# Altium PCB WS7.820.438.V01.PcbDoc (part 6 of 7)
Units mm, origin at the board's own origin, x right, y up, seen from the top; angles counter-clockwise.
Board outline 143.01 x 224 mm, 4 copper layers (Top Layer, G2, S3, Bottom Layer); 863 components, 638 nets, 2623 pads, 4664 vias.
Unrouted connection lines stored in the file: 16.
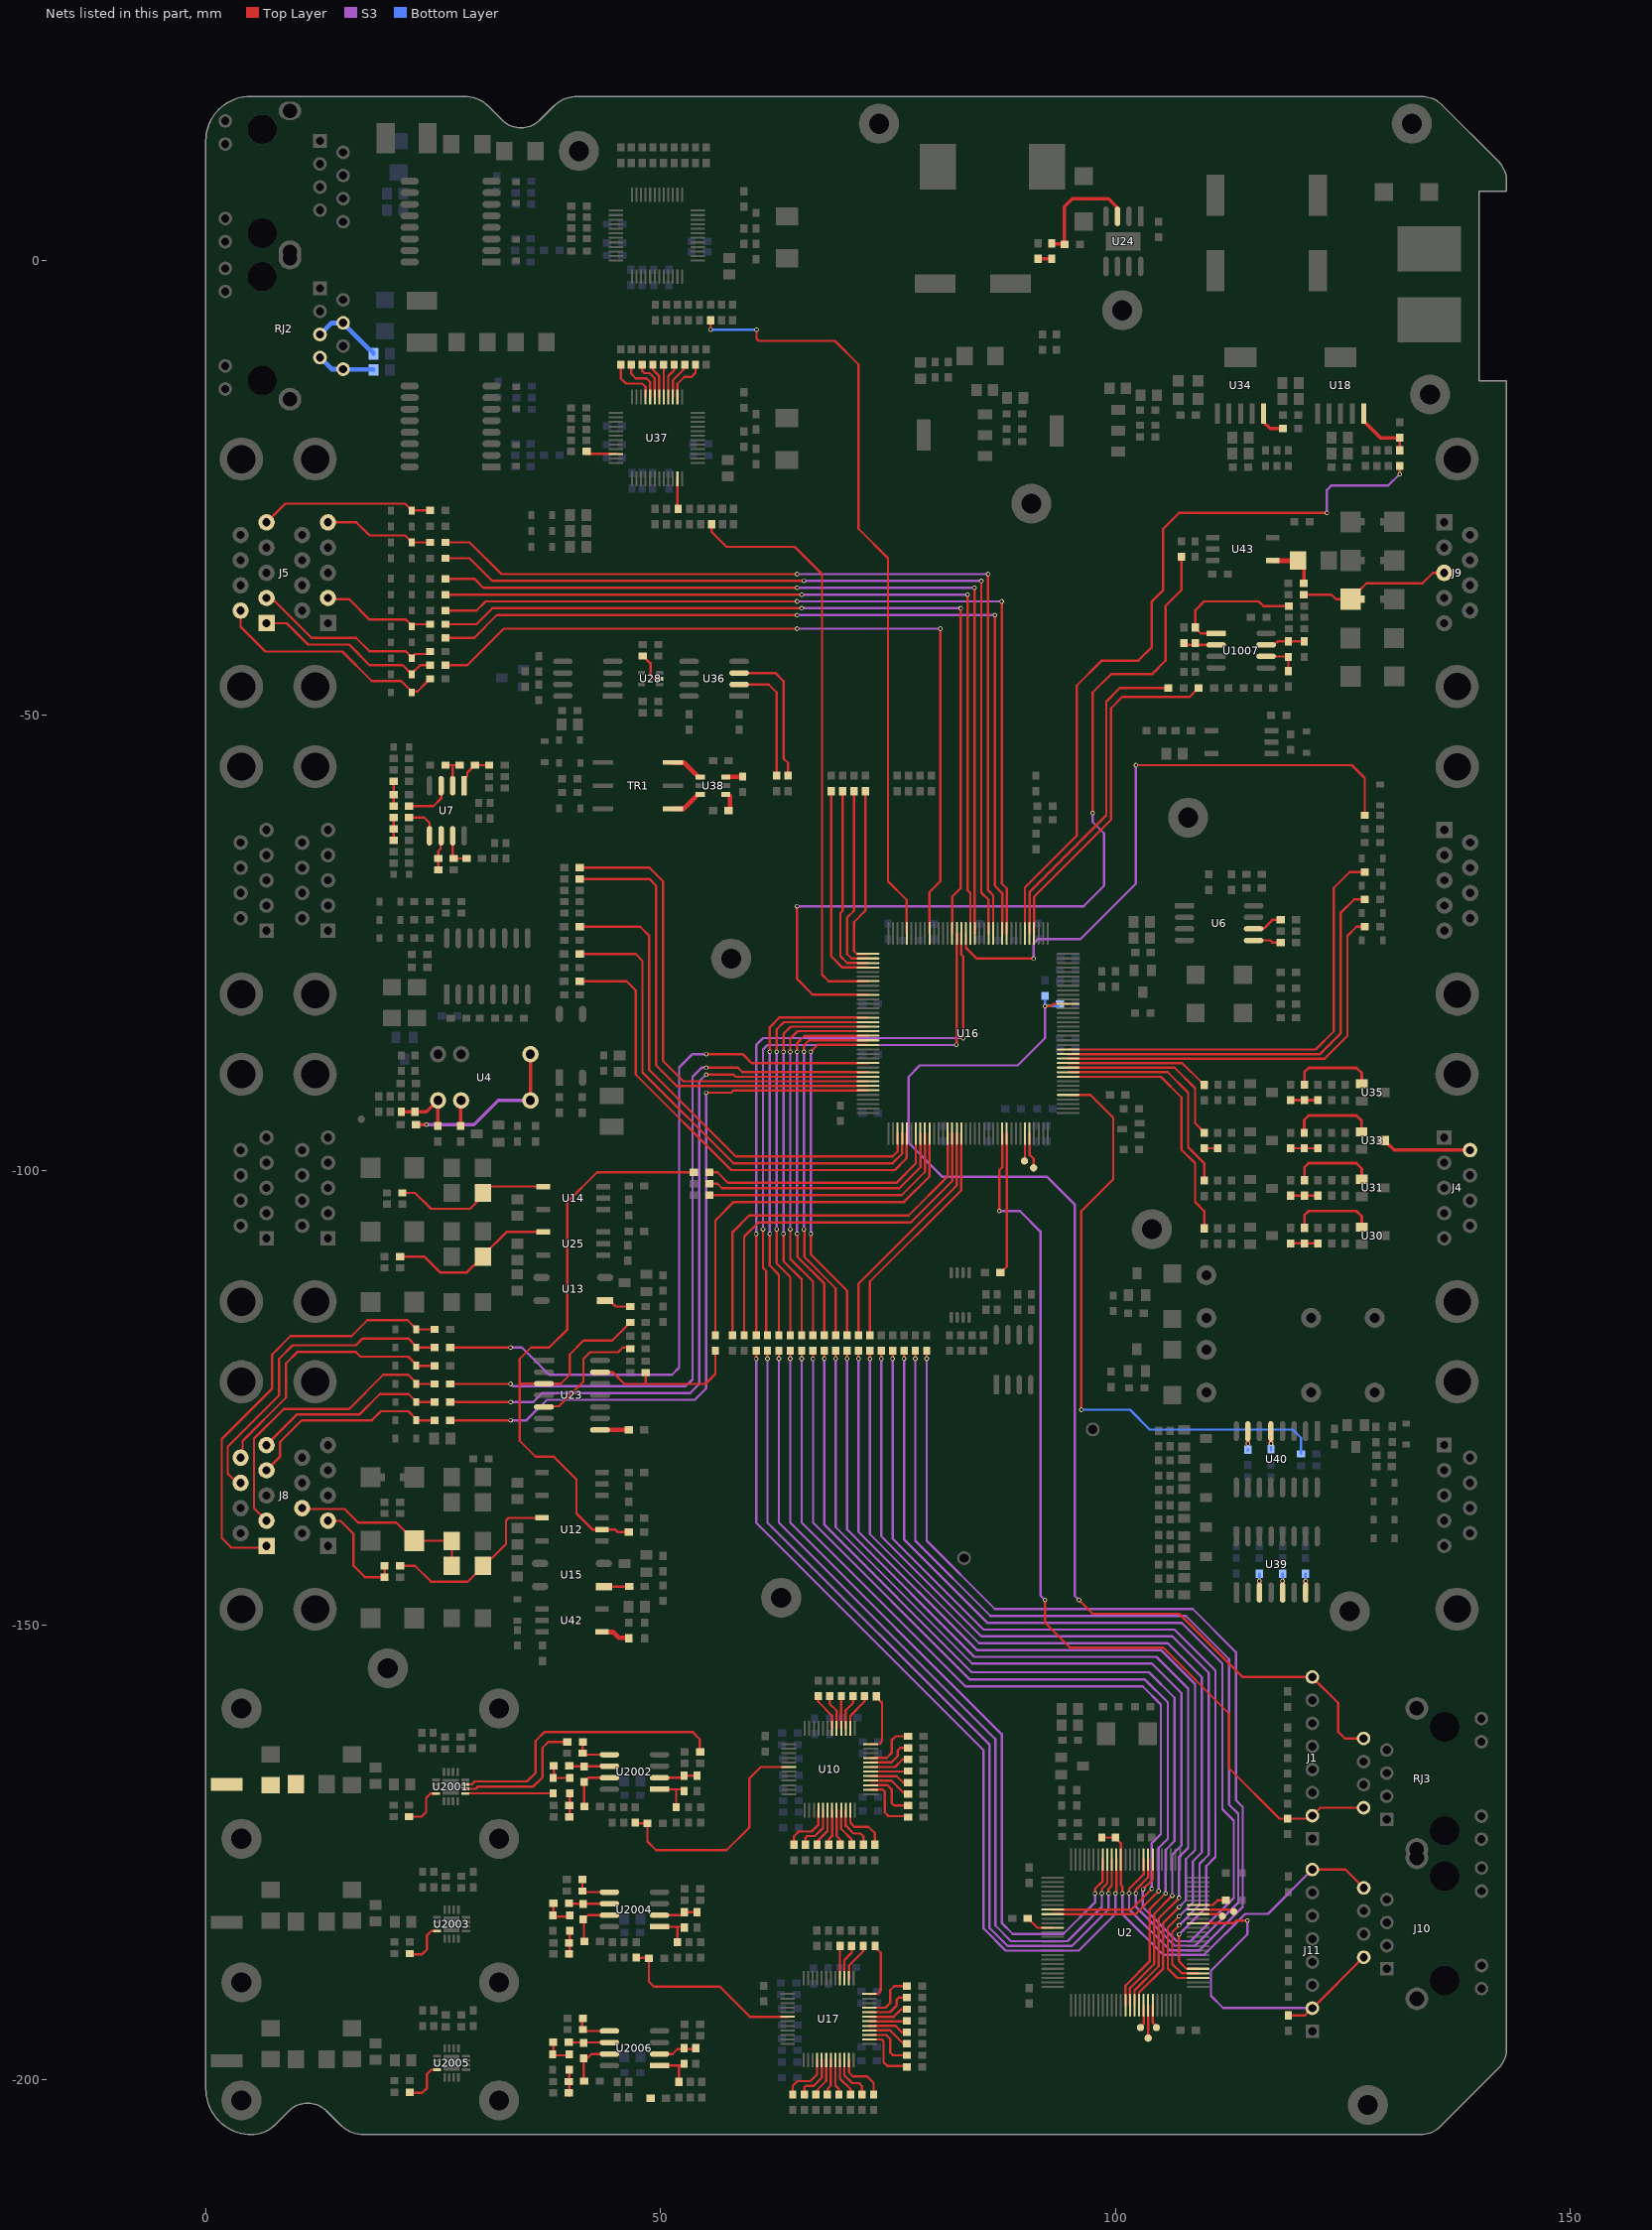
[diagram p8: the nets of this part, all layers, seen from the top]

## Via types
v1: diameter 0.508, hole 0.305, Top Layer to Bottom Layer, tented both sides, 4404 vias
v2: diameter 0.508, hole 0.3, Top Layer to Bottom Layer, tented both sides, 200 vias
v3: diameter 0.813, hole 0.508, Top Layer to Bottom Layer, tented both sides, 31 vias
v4: diameter 0.457, hole 0.305, Top Layer to Bottom Layer, tented both sides, 10 vias
v5: diameter 0.66, hole 0.406, Top Layer to Bottom Layer, tented both sides, 9 vias
v6: diameter 0.762, hole 0.406, Top Layer to Bottom Layer, tented both sides, 6 vias
v7: diameter 0.711, hole 0.406, Top Layer to Bottom Layer, tented both sides, 4 vias

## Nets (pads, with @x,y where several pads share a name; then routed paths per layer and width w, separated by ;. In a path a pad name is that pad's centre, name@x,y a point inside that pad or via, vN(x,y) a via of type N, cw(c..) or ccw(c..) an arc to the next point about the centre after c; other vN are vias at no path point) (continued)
NetR92_1: R92.1 U6.6 | length 3.4
  Top Layer w0.254: U6.6@115.19,-73.49 115.256,-73.424 116.326,-73.424 117.25,-72.5 R92.1@118.15,-72.5
NetR93_1: R93.1 U6.5 | length 3.1
  Top Layer w0.254: U6.5@115.19,-74.76 115.201,-74.75 117,-74.75 117.25,-75 R93.1@118.15,-75
NetR94_2: R94.2 U16.125 | length 26.5
  Top Layer w0.254: R94.2@73,-118.359 R94.2@73,-118.15 73,-112.25 83.051,-102.199 U16.125@83.051,-95.987
NetR95_2: R95.2 U16.124 | length 26.8
  Top Layer w0.254: R95.2@71.75,-118.3 71.75,-112.5 82.551,-101.699 U16.124@82.551,-95.987
NetR96_2: R96.2 U16.40 | length 38.8
  Top Layer w0.254: U16.40@91.051,-73.987 91.051,-69.949 99.5,-61.5 99.5,-49.25 100.75,-48 108.15,-48 R96.2@109.15,-47
NetR97_2: R97.2 U16.41 | length 36.4
  Top Layer w0.254: U16.41@90.551,-73.987 90.551,-69.449 99,-61 99,-48.5 100.5,-47 R97.2@105.75,-47
NetR98_2: R98.2 U16.93 | length 39.4
  Top Layer w0.254: v1(66.5,-107) 66.5,-109.25 70.5,-113.25 R98.2@70.5,-118.15 ; v1(66.5,-87) 67.261,-86.239 ; 67.25,-86.239 67.261,-86.239 ; U16.93@72.75,-86.239 67.261,-86.239
  S3 w0.254: v1(66.5,-107) v1(66.5,-87)
NetR99_1: R99.1 U17.40 | length 3.4
  Top Layer w0.254: U17.40@69.704,-188.809 69.704,-185.416 R99.1@69.724,-185.396
NetR100_2: R100.2 U16.92 | length 40.5
  Top Layer w0.254: v1(65.75,-106.5) 65.799,-106.549 65.799,-109.549 69.25,-113 R100.2@69.25,-118.15 ; v1(65.75,-87) 65.75,-86.288 66.311,-85.727 U16.92@72.75,-85.727
  S3 w0.254: v1(65.75,-106.5) v1(65.75,-87)
NetR101_1: R101.1 R166.1 U24.3 | length 12.9
  Top Layer w0.381: R166.1@93,1.85 93.05,1.8 94.35,1.8 R101.1@94.4,1.75 ; R101.1@94.4,2 94.4,5.9 95.25,6.75 99.25,6.75 100.181,5.819 100.181,4.867 U24.3@100.223,4.825
NetR102_1: R102.1 R166.2 | length 1.5
  Top Layer w0.381: R102.1@91.5,0.15 R166.2@93,0.15
NetR103_1: R103.1 R144.1 R146.2 U4.1 | length 7.5
  Top Layer w0.381: R103.1@21.5,-93.6 R144.1@23,-93.6 24.266,-93.6 U4.1@25.513,-92.354 ; R146.2@25.5,-95.15 25.513,-95.137 U4.1@25.513,-92.354 ; U4.1@25.5,-92.25 25.513,-92.263 U4.1@25.513,-92.354 ; U4.1@25.525,-92.341 U4.1@25.513,-92.354
NetR104_1: R104.1 U4.2 | length 2.7
  Top Layer w0.381: R104.1@28,-95.15 28.033,-95.117 28.033,-92.533 U4.2@28,-92.5
NetR105_2: R105.2 U42.1 | length 3.2
  Top Layer w0.508: U42.1@43.55,-150.77 44.77,-150.77 45.394,-151.394 46.494,-151.394 R105.2@46.5,-151.4
NetR106_1: R106.1 U16.10 | length 24.5
  Top Layer w0.254: U16.10@94.801,-89.237 105.737,-89.237 108,-91.5 108,-97.5 109.75,-99.25 R106.1@109.75,-101.15
NetR107_1: R107.1 U16.13 | length 45
  Top Layer w0.254: U16.13@94.801,-87.737 123.013,-87.737 125.5,-85.25 125.5,-74.25 126.5,-73.25 R107.1@127.4,-73.25
NetR111_2: R111.2 U16.91 | length 41.5
  Top Layer w0.254: v1(65,-107) 65.049,-107.049 65.049,-109.549 68,-112.5 R111.2@68,-118.15 ; v1(65,-87) 65,-86.038 65.801,-85.237 U16.91@72.801,-85.237
  S3 w0.254: v1(65,-107) v1(65,-87)
NetR112_1: R112.1 U17.39 | length 3.7
  Top Layer w0.254: U17.39@70.204,-188.809 70.204,-186.82 71.005,-186.019 71.005,-185.407 R112.1@70.994,-185.396
NetR113_2: R113.2 U16.90 | length 42.5
  Top Layer w0.254: v1(64.25,-106.5) 64.25,-109.75 66.75,-112.25 R113.2@66.75,-118.15 ; v1(64.25,-87) 64.25,-85.538 65.061,-84.727 ; 65.038,-84.727 65.061,-84.727 ; U16.90@72.75,-84.727 65.061,-84.727
  S3 w0.254: v1(64.25,-106.5) v1(64.25,-87)
NetR114_1: R114.1 U17.38 | length 4.1
  Top Layer w0.254: U17.38@70.704,-188.809 70.704,-187.428 72.264,-185.868 R114.1@72.264,-185.396
NetR115_1: R115.1 U16.56 | length 66.6
  Top Layer w0.254: R115.1@60.5,-118.15 v1(60.5,-107) ; U16.56@83.051,-73.987 83.051,-76.313 83.25,-76.512 v1(83.25,-85.5)
  S3 w0.254: v1(60.5,-107) 60.5,-86.25 61.25,-85.5 v1(83.25,-85.5)
NetR116_2: R116.2 U16.46 | length 98.3
  Top Layer w0.254: R116.2@26.35,-38.5 29.75,-38.5 30.75,-37.5 v1(65,-37.5) ; v1(87.5,-37.5) 87.5,-68.5 88.051,-69.051 U16.46@88.051,-73.987
  S3 w0.254: v1(65,-37.5) v1(87.5,-37.5)
NetR117_1: R117.1 U17.36 | length 6.5
  Top Layer w0.254: U17.36@72.954,-190.559 73.847,-190.559 74.201,-190.206 74.201,-186.031 R117.1@73.576,-185.406
NetR118_1: R118.1 U17.33 | length 5.9
  Top Layer w0.254: U17.33@72.954,-192.059 74.719,-192.059 75.247,-191.531 75.247,-190.125 75.69,-189.682 R118.1@77.055,-189.682
NetR119_2: R119.2 U16.89 | length 43.6
  Top Layer w0.254: v1(63.5,-107) 63.5,-110 65.5,-112 R119.2@65.5,-118.15 ; v1(63.5,-87) 63.5,-85.038 64.301,-84.237 U16.89@72.801,-84.237
  S3 w0.254: v1(63.5,-107) v1(63.5,-87)
NetR122_1: R122.1 U17.32 | length 5.1
  Top Layer w0.254: U17.32@72.954,-192.559 75.21,-192.559 75.933,-191.836 75.933,-191.201 76.182,-190.952 R122.1@77.055,-190.952
NetR123_1: R123.1 U16.57 | length 65.3
  Top Layer w0.254: v1(61.25,-106.5) 61.25,-110.75 61.603,-111.103 61.603,-118.003 R123.1@61.75,-118.15 ; v1(82.5,-86.217) 82.5,-86.148 82.551,-86.097 U16.57@82.551,-73.987
  S3 w0.254: v1(61.25,-106.5) 61.25,-86.75 61.75,-86.25 63,-86.25 82.467,-86.25 v1(82.5,-86.217)
NetR124_1: R124.1 U17.31 | length 4.4
  Top Layer w0.254: U17.31@72.954,-193.059 75.624,-193.059 76.462,-192.222 R124.1@77.055,-192.222
NetR125_1: R125.1 U17.30 | length 4.1
  Top Layer w0.254: U17.30@72.954,-193.559 76.987,-193.559 R125.1@77.055,-193.492
NetR126_1: R126.1 U17.29 | length 4.4
  Top Layer w0.254: U17.29@72.954,-194.059 75.808,-194.059 76.511,-194.762 R126.1@77.055,-194.762
NetR127_1: R127.1 U16.113 | length 53.2
  Top Layer w0.254: R127.1@41.1,-79.25 46.25,-79.25 47.25,-80.25 47.25,-89.5 57.75,-100 75.75,-100 77.051,-98.699 U16.113@77.051,-95.987
NetR128_1: R128.1 U16.112 | length 54.8
  Top Layer w0.254: R128.1@41.1,-76.25 47.25,-76.25 48,-77 48,-89.25 58,-99.25 75.5,-99.25 76.551,-98.199 U16.112@76.551,-95.987
NetR129_1: R129.1 U16.111 | length 56.2
  Top Layer w0.254: R129.1@41.1,-73.25 47.75,-73.25 48.75,-74.25 48.75,-89 58.25,-98.5 75.5,-98.5 76.051,-97.949 U16.111@76.051,-95.987
NetR130_1: R130.1 U17.28 | length 4.7
  Top Layer w0.254: U17.28@72.954,-194.559 75.237,-194.559 76.709,-196.032 R130.1@77.055,-196.032
NetR131_1: R131.1 U17.27 | length 5.9
  Top Layer w0.254: U17.27@72.954,-195.059 74.797,-195.059 75.247,-195.509 75.247,-197.008 75.541,-197.302 R131.1@77.055,-197.302
NetR132_1: R132.1 U17.26 | length 6.7
  Top Layer w0.254: U17.26@72.954,-195.559 74.306,-195.559 74.511,-195.763 74.511,-198.049 74.917,-198.456 76.939,-198.456 R132.1@77.055,-198.572
NetR133_2: R133.2 U17.16 | length 5.7
  Top Layer w0.254: R133.2@64.517,-201.603 64.517,-200.661 65.036,-200.142 66.459,-200.142 67.204,-199.396 U17.16@67.204,-197.809
NetR134_2: R134.2 U17.17 | length 5.1
  Top Layer w0.254: R134.2@65.787,-201.603 65.787,-200.839 65.976,-200.65 66.814,-200.65 67.704,-199.76 U17.17@67.704,-197.809
NetR135_2: R135.2 U17.18 | length 4.3
  Top Layer w0.254: R135.2@67.057,-201.603 67.057,-201.245 68.204,-200.098 U17.18@68.204,-197.809
NetR136_2: R136.2 U17.19 | length 4
  Top Layer w0.254: R136.2@68.327,-201.603 68.358,-201.573 68.358,-200.98 68.704,-200.634 U17.19@68.704,-197.809
NetR137_2: R137.2 U17.20 | length 4
  Top Layer w0.254: U17.20@69.204,-197.809 69.204,-200.627 69.597,-201.02 R137.2@69.597,-201.603
NetR138_2: R138.2 U17.21 | length 4.3
  Top Layer w0.254: U17.21@69.704,-197.809 69.704,-199.857 70.867,-201.02 R138.2@70.867,-201.603
NetR139_2: R139.2 U17.22 | length 5
  Top Layer w0.254: U17.22@70.204,-197.809 70.204,-199.509 71.056,-200.361 71.818,-200.361 72.137,-200.68 R139.2@72.137,-201.603
NetR140_2: R140.2 U17.23 | length 5.8
  Top Layer w0.254: U17.23@70.704,-197.809 70.704,-199.171 71.158,-199.624 72.707,-199.624 73.407,-200.324 R140.2@73.407,-201.603
NetR141_2: R141.2 U16.88 | length 44.6
  Top Layer w0.254: v1(62.75,-106.5) 62.75,-110.25 64.25,-111.75 R141.2@64.25,-118.15 ; v1(62.75,-87) 62.75,-84.538 63.551,-83.737 U16.88@72.801,-83.737
  S3 w0.254: v1(62.75,-106.5) v1(62.75,-87)
NetR142_2: R142.2 U16.87 | length 45.5
  Top Layer w0.254: v1(62,-107) 62,-110.5 63,-111.5 R142.2@63,-118.15 ; v1(62,-87) 62,-84.288 63.061,-83.227 ; 63.038,-83.227 63.061,-83.227 ; U16.87@72.75,-83.227 63.061,-83.227
  S3 w0.254: v1(62,-107) v1(62,-87)
NetR145_2: R145.2 U2.94 | length 3.3
  Top Layer w0.254: U2.94@109.096,-180.781 110.719,-180.781 111.25,-180.25 R145.2@112.15,-180.25
NetR149_2: R149.2 R150.1 R154.2 | length 2.8
  Top Layer w0.254: R150.1@20.65,-60 R149.2@20.65,-57.25
NetR150_2: R150.2 U7.3 | length 5.3
  Top Layer w0.254: R150.2@22.35,-60 25,-60 25.865,-59.135 U7.3@25.865,-57.75
NetR151_1: R151.1 R161.2 U7.1 | length 4.3
  Top Layer w0.254: U7.1@28.405,-57.75 28.405,-56.975 28.75,-56.63 28.75,-56.3 29.55,-55.5 R161.2@29.6,-55.5 R151.1@31.15,-55.5
NetR152_1: R152.1 U16.5 | length 66.7
  Top Layer w0.254: U16.5@94.801,-91.737 97.237,-91.737 99.75,-94.25 99.75,-101 96.25,-104.5 v1(96.25,-126.345)
  Bottom Layer w0.254: v1(96.25,-126.345) 101.595,-126.345 103.774,-128.524 119.507,-128.524 120.396,-129.413 R152.1@120.396,-131.191
NetR158_2: R158.2 R161.1 U7.2 | length 3.7
  Top Layer w0.254: R158.2@26.35,-55.5 27,-55.5 ; U7.2@27.135,-57.75 27.135,-55.635 27,-55.5 ; R161.1@27.75,-55.5 27,-55.5
NetR160_1: R160.1 U34.5 | length 3.4
  Top Layer w0.381: U34.5@116.262,-16.848 116.262,-17.762 117,-18.5 R160.1@118.4,-18.5
NetR162_1: R162.1 U16.79 | length 64.3
  Top Layer w0.254: R162.1@55.596,-29.011 55.596,-29.846 57.25,-31.5 64.75,-31.5 67.75,-34.5 67.75,-78.5 68.487,-79.237 U16.79@72.801,-79.237
NetR164_2: R164.2 U2.37 | length 3.2
  Top Layer w0.254: R164.2@90.35,-182.25 90.4,-182.25 91.431,-183.281 U2.37@93.096,-183.281
NetR165_2: R165.2 U16.68 | length 84.2
  Top Layer w0.254: R165.2@55.479,-6.595 55.499,-6.615 v1(55.499,-7.62) ; v1(60.547,-7.638) 60.547,-8.629 60.782,-8.865 69.151,-8.865 71.75,-11.464 71.75,-29.5 75,-32.75 75,-68.25 77.051,-70.301 U16.68@77.051,-73.987
  Bottom Layer w0.254: v1@55.499,-7.638 v1(60.547,-7.638)
NetR167_2: R167.2 U16.47 | length 96.8
  Top Layer w0.254: R167.2@26.35,-41.5 29.5,-41.5 32,-39 v1(65,-39) ; v1(86.75,-39) 86.75,-68.75 87.551,-69.551 U16.47@87.551,-73.987
  S3 w0.254: v1(65,-39) v1(86.75,-39)
NetR168_2: R168.2 U16.49 | length 100.8
  Top Layer w0.254: R168.2@26.35,-31 29,-31 32.5,-34.5 v1(65,-34.5) ; v1(86,-34.5) 86,-69.25 86.551,-69.801 U16.49@86.551,-73.987
  S3 w0.254: v1(65,-34.5) v1(86,-34.5)
NetR169_2: R169.2 U16.50 | length 99
  Top Layer w0.254: R169.2@26.35,-32.75 29,-32.75 31.5,-35.25 65.717,-35.25 v1(65.75,-35.217) ; v1(85.25,-35.25) 85.25,-69.5 86.051,-70.301 U16.50@86.051,-73.987
  S3 w0.254: v1(65.75,-35.217) 65.767,-35.233 85.233,-35.233 v1(85.25,-35.25)
NetR170_2: R170.2 U16.53 | length 96.6
  Top Layer w0.254: R170.2@26.35,-35 29.5,-35 30.5,-36 v1(65,-36) ; v1(84.5,-36) 84.5,-72.831 84.551,-72.881 U16.53@84.551,-73.987
  S3 w0.254: v1(65,-36) v1(84.5,-36)
NetR171_2: R171.2 U16.54 | length 94.8
  Top Layer w0.254: R171.2@26.35,-36.75 v1(65.5,-36.75) ; v1(83.75,-36.75) 83.75,-69.25 84.051,-69.551 U16.54@84.051,-73.987
  S3 w0.254: v1(65.5,-36.75) v1(83.75,-36.75)
NetR173_1: R173.1 U16.9 | length 28.8
  Top Layer w0.254: U16.9@94.801,-89.737 104.987,-89.737 107.25,-92 107.25,-97.75 108.75,-99.25 108.75,-103.5 109.75,-104.5 R173.1@109.75,-106.4
NetR174_1: R174.1 U16.14 | length 47.4
  Top Layer w0.254: U16.14@94.801,-87.237 94.813,-87.25 122.5,-87.25 124.75,-85 124.75,-71.75 126.25,-70.25 R174.1@127.4,-70.25
NetR175_1: R175.1 U16.15 | length 49.9
  Top Layer w0.254: U16.15@94.801,-86.737 122.013,-86.737 124,-84.75 124,-69 125.75,-67.25 R175.1@127.4,-67.25
NetR176_1: R176.1 U16.42 | length 84
  Top Layer w0.254: U16.42@90.051,-73.987 90.051,-68.949 95.75,-63.25 95.75,-46.75 98.5,-44 102.5,-44 104,-42.5 104,-37.5 105.25,-36.25 105.25,-29.5 107,-27.75 v1(123.25,-27.75) ; v1(131.25,-23.5) R176.1@131.25,-22.6
  S3 w0.254: v1(123.25,-27.75) 123.25,-25.25 123.75,-24.75 130,-24.75 v1(131.25,-23.5)
NetR177_2: R177.2 U16.102 | length 52.7
  Top Layer w0.254: R177.2@41.1,-68 48.75,-68 49.5,-68.75 49.5,-88.5 51.737,-90.737 U16.102@72.801,-90.737
NetR178_2: R178.2 U16.101 | length 53
  Top Layer w0.254: R178.2@41.1,-66.75 48.75,-66.75 50.25,-68.25 50.25,-88 52.487,-90.237 ; 52.5,-90.237 U16.101@72.801,-90.237
NetR184_1: R184.1 R185.1 U12.1 | length 20.8
  Top Layer w0.254: R185.1@21.35,-143.5 23,-143.5 24.75,-145.25 28.8,-145.25 30.4,-143.65 30.45,-143.65 33,-141.1 33,-138.5 33.27,-138.23 U12.1@36.95,-138.23
NetR188_2: R188.2 U13.1 | length 2.9
  Top Layer w0.254: U13.1@43.9,-114.345 44.4,-114.345 45.055,-115 R188.2@46.5,-115
NetR192_2: R192.2 U15.1 | length 2.8
  Top Layer w0.254: U15.1@43.75,-145.77 46.48,-145.77 R192.2@46.5,-145.75
NetR194_1: R194.1 R198.1 U14.1 | length 17.4
  Top Layer w0.254: R198.1@21.6,-102.5 23,-102.5 24.75,-104.25 29.05,-104.25 30.45,-102.85 30.45,-102.65 31.295,-101.805 U14.1@37.1,-101.805
NetR203_2: R203.2 U23.5 | length 13.7
  Top Layer w0.254: U23.5@37.164,-126.02 37.23,-125.954 38.796,-125.954 41.5,-123.25 41.5,-120.75 42.235,-120.015 45.339,-120.015 45.854,-119.5 R203.2@46.65,-119.5
NetR204_1: R204.1 R206.1 U25.1 | length 18.3
  Top Layer w0.254: R206.1@21.35,-109.5 24,-109.5 25.75,-111.25 28.7,-111.25 29.577,-110.373 29.677,-110.373 30.45,-109.6 R204.1@30.45,-109.5 ; R204.1@30.45,-109.4 33.045,-106.805 U25.1@37.1,-106.805
NetR205_1: R205.1 U23.8 | length 3.2
  Top Layer w0.508: U23.8@43.336,-128.56 R205.1@46.5,-128.56
NetR208_1: R208.1 U16.12 | length 16
  Top Layer w0.254: U16.12@94.801,-88.237 107.337,-88.237 109.427,-90.327 109.477,-90.327 109.75,-90.6 R208.1@109.75,-90.65
NetR209_1: R209.1 U16.135 | length 15.6
  Top Layer w0.254: R209.1@87.35,-111.25 87.4,-111.25 87.673,-110.977 88.051,-110.599 U16.135@88.051,-95.987
NetR210_2: R210.2 U28.2 | length 3.7
  Top Layer w0.254: R210.2@48.032,-43.5 48.082,-43.5 48.882,-44.3 48.882,-45.632 49.25,-46 U28.2@49.882,-46
NetR211_2: R211.2 U36.2 | length 13.5
  Top Layer w0.254: U36.2@58.632,-46.635 61.885,-46.635 62.75,-47.5 62.75,-47.79 ; R211.2@62.75,-56.5 62.75,-47.75
NetR212_2: R212.2 U36.3 | length 15.8
  Top Layer w0.254: U36.3@58.632,-45.365 62.615,-45.365 63.5,-46.25 63.5,-54.75 64,-55.25 R212.2@64,-56.65
NetR213_2: R213.2 U16.97 | length 81.5
  Top Layer w0.254: R213.2@26.85,-119.5 v1(33.5,-119.5) ; v2(55,-87.25) 59,-87.25 59.987,-88.237 63.237,-88.237 U16.97@72.801,-88.237
  S3 w0.254: v1(33.5,-119.5) 34.75,-119.5 37.75,-122.5 51.25,-122.5 52.033,-121.717 52.033,-88.717 53.5,-87.25 v2(55,-87.25)
NetR214_2: R214.2 U16.63 | length 90
  Top Layer w0.254: R214.2@26.35,-44.5 28.75,-44.5 32.75,-40.5 v1(65,-40.5) ; U16.63@79.551,-73.987 79.551,-69.449 80.75,-68.25 v1(80.75,-40.5)
  S3 w0.254: v1(65,-40.5) v1(80.75,-40.5)
NetR215_2: R215.2 U16.58 | length 93.5
  Top Layer w0.254: R215.2@26.35,-40 29.75,-40 31.5,-38.25 v1(65.5,-38.25) ; U16.58@82.051,-73.987 82.051,-69.949 83,-69 83,-54.909 v1(83,-38.25)
  S3 w0.254: v1(65.5,-38.25) v1(83,-38.25)
NetR221_1: R221.1 U16.123 | length 41.7
  Top Layer w0.254: R221.1@59.182,-118.446 59.182,-107.315 60.747,-105.75 77.5,-105.75 82.051,-101.199 U16.123@82.051,-95.987
NetR222_1: R222.1 U16.122 | length 42.5
  Top Layer w0.254: R222.1@57.912,-118.405 57.912,-106.807 59.719,-105 77.25,-105 81.551,-100.699 U16.122@81.551,-95.987
NetR223_1: R223.1 U16.11 | length 20.2
  Top Layer w0.254: U16.11@94.801,-88.737 106.487,-88.737 108.75,-91 108.75,-94.85 109.75,-95.85 R223.1@109.75,-95.9
NetR224_2: R224.2 U4.5 U4.6 | length 18.8
  Top Layer w0.381: R224.2@23.1,-95 v1(24.25,-95) ; U4.5@35.685,-92.341 U4.6@35.685,-87.261
  S3 w0.381: v1(24.25,-95) 29.5,-95 32.159,-92.341 U4.5@35.685,-92.341
NetR229_2: R229.2 U16.103 | length 79.8
  Top Layer w0.254: R229.2@27.1,-127.5 v2(33.5,-127.5) ; v1(55,-91.5) 57.75,-91.5 58.013,-91.237 61.513,-91.237 U16.103@72.801,-91.237
  S3 w0.254: v2(33.5,-127.5) 35.25,-127.5 37.5,-125.25 53.75,-125.25 55,-124 v1(55,-91.5)
NetR230_2: R230.2 U16.100 | length 80.4
  Top Layer w0.254: R230.2@26.85,-125.5 v2(33.5,-125.5) ; v1(55,-89.5) 58,-89.5 58.237,-89.737 U16.100@72.801,-89.737
  S3 w0.254: v2(33.5,-125.5) 36,-125.5 37,-124.5 53.25,-124.5 54.25,-123.5 54.25,-90.25 v1(55,-89.5)
NetR231_2: R231.2 U16.99 | length 80.2
  Top Layer w0.254: R231.2@26.85,-123.5 v2(33.5,-123.5) ; v1(55,-88.75) 58.5,-88.75 58.987,-89.237 U16.99@72.801,-89.237
  S3 w0.254: v2(33.5,-123.5) 33.526,-123.5 33.776,-123.75 52.75,-123.75 53.5,-123 53.5,-89.75 54.5,-88.75 v1(55,-88.75)
NetR232_1: R232.1 U10.42 | length 4
  Top Layer w0.254: R232.1@67.324,-157.946 67.324,-158.447 68.844,-159.967 U10.42@68.844,-161.359
NetR233_1: R233.1 U10.41 | length 3.9
  Top Layer w0.254: R233.1@68.594,-157.819 68.594,-158.676 69.344,-159.426 U10.41@69.344,-161.359
NetR234_1: R234.1 U10.40 | length 3.4
  Top Layer w0.254: U10.40@69.844,-161.359 69.844,-157.966 R234.1@69.864,-157.946
NetR235_1: R235.1 U10.39 | length 3.7
  Top Layer w0.254: U10.39@70.344,-161.359 70.344,-159.37 71.145,-158.569 71.145,-157.957 R235.1@71.134,-157.946
NetR236_1: R236.1 U10.38 | length 4.1
  Top Layer w0.254: U10.38@70.844,-161.359 70.844,-159.978 72.404,-158.418 R236.1@72.404,-157.946
NetR237_1: R237.1 U10.36 | length 6.5
  Top Layer w0.254: U10.36@73.094,-163.109 73.987,-163.109 74.341,-162.756 74.341,-158.581 R237.1@73.716,-157.956
NetR238_1: R238.1 U10.33 | length 5.9
  Top Layer w0.254: U10.33@73.094,-164.609 74.859,-164.609 75.387,-164.081 75.387,-162.675 75.83,-162.232 R238.1@77.195,-162.232
NetR239_1: R239.1 U10.32 | length 5.1
  Top Layer w0.254: U10.32@73.094,-165.109 75.35,-165.109 76.073,-164.386 76.073,-163.751 76.322,-163.502 R239.1@77.195,-163.502
NetR240_1: R240.1 U10.31 | length 4.4
  Top Layer w0.254: U10.31@73.094,-165.609 75.764,-165.609 76.602,-164.772 R240.1@77.195,-164.772
NetR241_1: R241.1 U10.30 | length 4.1
  Top Layer w0.254: U10.30@73.094,-166.109 77.127,-166.109 R241.1@77.195,-166.042
NetR242_1: R242.1 U10.29 | length 4.4
  Top Layer w0.254: U10.29@73.094,-166.609 75.948,-166.609 76.651,-167.312 R242.1@77.195,-167.312
NetR243_1: R243.1 U10.28 | length 4.7
  Top Layer w0.254: U10.28@73.094,-167.109 75.377,-167.109 76.849,-168.582 R243.1@77.195,-168.582
NetR244_1: R244.1 U10.27 | length 5.9
  Top Layer w0.254: U10.27@73.094,-167.609 74.937,-167.609 75.387,-168.059 75.387,-169.558 75.681,-169.852 R244.1@77.195,-169.852
NetR245_1: R245.1 U10.26 | length 6.7
  Top Layer w0.254: U10.26@73.094,-168.109 74.446,-168.109 74.651,-168.313 74.651,-170.599 75.057,-171.006 77.079,-171.006 R245.1@77.195,-171.122
NetR246_2: R246.2 U10.16 | length 5.7
  Top Layer w0.254: R246.2@64.657,-174.153 64.657,-173.211 65.176,-172.692 66.599,-172.692 67.344,-171.946 U10.16@67.344,-170.359
NetR247_2: R247.2 U10.17 | length 5.1
  Top Layer w0.254: R247.2@65.927,-174.153 65.927,-173.389 66.116,-173.2 66.954,-173.2 67.844,-172.31 U10.17@67.844,-170.359
NetR248_2: R248.2 U10.18 | length 4.3
  Top Layer w0.254: R248.2@67.197,-174.153 67.197,-173.795 68.344,-172.648 U10.18@68.344,-170.359
NetR249_2: R249.2 U10.19 | length 4
  Top Layer w0.254: R249.2@68.467,-174.153 68.498,-174.123 68.498,-173.53 68.844,-173.184 U10.19@68.844,-170.359
NetR250_2: R250.2 U10.20 | length 4
  Top Layer w0.254: U10.20@69.344,-170.359 69.344,-173.177 69.737,-173.57 R250.2@69.737,-174.153
NetR251_2: R251.2 U10.21 | length 4.3
  Top Layer w0.254: U10.21@69.844,-170.359 69.844,-172.407 71.007,-173.57 R251.2@71.007,-174.153
NetR252_2: R252.2 U10.22 | length 5
  Top Layer w0.254: U10.22@70.344,-170.359 70.344,-172.059 71.196,-172.911 71.958,-172.911 72.277,-173.23 R252.2@72.277,-174.153
NetR253_2: R253.2 U10.23 | length 5.8
  Top Layer w0.254: U10.23@70.844,-170.359 70.844,-171.721 71.298,-172.174 72.847,-172.174 73.547,-172.874 R253.2@73.547,-174.153
NetR254_1: R254.1 R256.1 R258.2 | length 3
  Top Layer w0.254: R258.2@119.27,-108.06 R256.1@120.77,-108.06 R254.1@122.27,-108.06
NetR255_1: R255.1 R257.1 R259.2 | length 3
  Top Layer w0.254: R259.2@119.27,-102.81 R257.1@120.77,-102.81 R255.1@122.27,-102.81
NetR256_2: R256.2 U30.1 | length 9.3
  Top Layer w0.305: R256.2@120.77,-106.36 120.77,-104.98 121.25,-104.5 126.5,-104.5 127.07,-105.07 U30.1@127.07,-106.26
NetR257_2: R257.2 U31.1 | length 9.3
  Top Layer w0.305: R257.2@120.77,-101.11 120.77,-99.73 121.25,-99.25 126.5,-99.25 127.07,-99.82 U31.1@127.07,-101.01
NetR276_2: R276.2 RJ2.4 RJ2.5 | length 7.9
  Bottom Layer w0.508: RJ2.5@12.55,-8.162 13.82,-6.892 RJ2.4@15.09,-6.892 ; RJ2.4@15.09,-6.884 15.09,-6.937 18.032,-9.879 18.132,-9.879 18.428,-10.175 R276.2@18.428,-10.275
NetR278_2: R278.2 RJ2.7 RJ2.8 | length 6.4
  Bottom Layer w0.508: RJ2.7@12.55,-10.694 13.82,-11.964 RJ2.8@15.09,-11.964 15.134,-12.009 18.384,-12.009 R278.2@18.428,-12.053
NetR279_1: R279.1 U37.45 | length 5.7
  Top Layer w0.254: R279.1@45.612,-11.485 45.612,-12.972 46.196,-13.556 47.974,-13.556 48.342,-13.925 U37.45@48.342,-15.025
NetR282_2: R282.2 U37.10 | length 3.2
  Top Layer w0.254: R282.2@41.89,-21.233 41.932,-21.275 U37.10@45.092,-21.275
NetR283_1: R283.1 U37.44 | length 5.1
  Top Layer w0.254: R283.1@46.786,-11.485 46.786,-12.496 47.263,-12.972 48.431,-12.972 48.842,-13.383 U37.44@48.842,-15.025
NetR284_1: R284.1 U37.43 | length 4.5
  Top Layer w0.254: R284.1@47.961,-11.485 47.961,-12.172 48.202,-12.413 48.787,-12.413 49.342,-12.969 U37.43@49.342,-15.025
NetR285_2: R285.2 U37.23 | length 3.3
  Top Layer w0.254: U37.23@51.842,-24.025 51.842,-27.235 R285.2@51.918,-27.311
NetR286_2: R286.2 U37.38 | length 4.8
  Top Layer w0.254: U37.38@51.842,-15.025 51.842,-13.574 52.597,-12.82 53.384,-12.82 53.835,-12.369 R286.2@53.835,-11.485
NetR287_2: R287.2 U37.39 | length 4.1
  Top Layer w0.254: U37.39@51.342,-15.025 51.342,-13.185 52.66,-11.867 R287.2@52.66,-11.485
NetR288_2: R288.2 U37.40 | length 3.8
  Top Layer w0.254: U37.40@50.842,-15.025 50.842,-12.72 51.485,-12.077 R288.2@51.485,-11.485
NetR289_2: R289.2 U37.41 | length 3.6
  Top Layer w0.254: R289.2@50.311,-11.485 50.342,-11.517 U37.41@50.342,-15.025
NetR290_2: R290.2 U37.42 | length 3.8
  Top Layer w0.254: R290.2@49.136,-11.485 49.136,-12.026 49.842,-12.732 U37.42@49.842,-15.025
NetR292_1: R292.1 R294.1 R296.2 | length 3
  Top Layer w0.254: R296.2@119.25,-97.6 R292.1@122.25,-97.6
NetR293_1: R293.1 R295.1 R297.2 | length 3
  Top Layer w0.305: R297.2@119.27,-92.31 R295.1@120.77,-92.31 R293.1@122.27,-92.31
NetR294_2: R294.2 U33.1 | length 9.4
  Top Layer w0.305: R294.2@120.75,-95.9 120.75,-94.5 121.25,-94 126.5,-94 127.05,-94.55 U33.1@127.05,-95.8
NetR295_2: R295.2 U35.1 | length 9.3
  Top Layer w0.305: R295.2@120.77,-90.61 120.77,-89.23 121.25,-88.75 126.5,-88.75 127.07,-89.32 U35.1@127.07,-90.51
NetR302_2: R302.2 U16.82 | length 94.5
  Top Layer w0.254: v1(65,-71) 65,-79 66.737,-80.737 U16.82@72.801,-80.737 ; v1(97.5,-60.75) 97.5,-47.5 99.5,-45.5 104,-45.5 105.5,-44 105.5,-38 107.25,-36.25 R302.2@107.25,-32.6
  S3 w0.254: v1(65,-71) 96.5,-71 98.75,-68.75 98.75,-63 97.5,-61.75 v1(97.5,-60.75)
NetR303_2: R303.2 U38.1 | length 2.1
  Top Layer w0.508: U38.1@57.157,-58.7 57.382,-58.7 57.607,-58.925 R303.2@57.607,-60.5
NetR305_2: R305.2 U38.3 | length 1.9
  Top Layer w0.508: U38.3@57.157,-56.8 57.178,-56.779 58.978,-56.779 R305.2@59.007,-56.75
NetR306_2: R306.2 R307.1 R319.2 | length 2.5
  Top Layer w0.254: R306.2@20.65,-63.75 R319.2@20.65,-62.5 R307.1@20.65,-61.25
NetR307_2: R307.2 U7.5 | length 3.7
  Top Layer w0.254: R307.2@22.5,-61.25 24,-61.25 24.595,-61.845 U7.5@24.595,-63.25
NetR308_1: R308.1 R352.2 U43.1 | length 5.5
  Top Layer w0.381: R308.1@120.05,-33.1 120.7,-33.75 R352.2@120.7,-35.5
  Top Layer w0.508: U43.1@117.3,-33.02 119.98,-33.02 R308.1@120,-33 ; R308.1@120.05,-33.1 R308.1@120.05,-33
NetR309_1: R309.1 U16.118 | length 42.9
  Top Layer w0.254: R309.1@56.007,-118.199 56.007,-105.537 58.044,-103.5 76.75,-103.5 79.551,-100.699 U16.118@79.551,-95.987
NetR310_1: R310.1 U16.117 | length 29
  Top Layer w0.254: R310.1@55.35,-102.75 76.5,-102.75 79.051,-100.199 U16.117@79.051,-95.987
NetR311_1: R311.1 U16.116 | length 28.1
  Top Layer w0.254: R311.1@55.35,-101.5 56.25,-101.5 56.75,-102 76.25,-102 78.551,-99.699 U16.116@78.551,-95.987
NetR312_1: R312.1 U16.115 | length 27.3
  Top Layer w0.254: R312.1@55.35,-100.25 56.25,-100.25 57.406,-101.406 75.918,-101.406 78.051,-99.274 U16.115@78.051,-95.987
NetR318_1: R318.1 R321.2 U7.7 | length 3.9
  Top Layer w0.254: U7.7@27.135,-63.25 27.135,-65.635 R321.2@27.25,-65.75 R318.1@28.65,-65.75
NetR320_2: R320.2 R321.1 U7.6 | length 3.9
  Top Layer w0.254: R320.2@25.55,-67 R321.1@25.55,-65.75 25.55,-64.95 25.799,-64.701 25.799,-63.316 U7.6@25.865,-63.25
NetR322_2: R322.2 U16.55 | length 68
  Top Layer w0.254: U16.55@83.551,-73.987 83.551,-75.551 84.75,-76.75 v1(91,-76.75) ; v1(102.25,-55.5) 126,-55.5 127.4,-56.9 R322.2@127.4,-61
  S3 w0.254: v1(91,-76.75) 91,-75.1 91.5,-74.6 96.15,-74.6 102.25,-68.5 v1(102.25,-55.5)
NetR326_2: R326.2 U16.74 | length 20.7
  Top Layer w0.254: R326.2@71.25,-58.35 71.25,-71.5 70.5,-72.25 70.5,-76.25 70.987,-76.737 U16.74@72.801,-76.737
NetR327_2: R327.2 U16.73 | length 19.6
  Top Layer w0.254: R327.2@72.5,-58.5 72.5,-71.5 71.25,-72.75 71.25,-75.916 71.571,-76.237 U16.73@72.801,-76.237
NetR328_2: R328.2 U16.75 | length 21.6
  Top Layer w0.254: R328.2@70,-58.35 70,-71.5 69.75,-71.75 69.75,-76.5 70.487,-77.237 U16.75@72.801,-77.237
NetR329_2: R329.2 U16.76 | length 22.7
  Top Layer w0.254: R329.2@68.75,-58.35 68.75,-76.5 69.987,-77.737 U16.76@72.801,-77.737
NetR330_2: R330.2 U39.3 | length 2.1
  Top Layer w0.508: v1(115.824,-145.161) 115.824,-146.425 U39.3@115.835,-146.436
  Bottom Layer w0.254: v1(115.824,-145.161) R330.2@115.824,-144.36
NetR332_2: R332.2 U39.5 | length 2.1
  Top Layer w0.254: v1(118.364,-145.161) v1@118.369,-145.166 ; U39.5@118.369,-146.431 U39.5@118.375,-146.436
  Top Layer w0.508: U39.5@118.369,-146.431 v1@118.369,-145.166
  Bottom Layer w0.254: v1(118.364,-145.161) R332.2@118.364,-144.36
NetR334_2: R334.2 U40.5 | length 2.1
  Top Layer w0.508: v1(117.094,-130.048) U40.5@117.094,-128.702
  Bottom Layer w0.254: R334.2@117.094,-130.81 R334.2@117.094,-130.683 v1(117.094,-130.048)
NetR336_2: R336.2 U39.7 | length 2.1
  Top Layer w0.254: v1(120.904,-145.161) v1@120.91,-145.167 ; U39.7@120.91,-146.431 U39.7@120.915,-146.436
  Top Layer w0.508: U39.7@120.91,-146.431 v1@120.91,-145.167
  Bottom Layer w0.254: v1(120.904,-145.161) R336.2@120.904,-144.36
NetR338_2: R338.2 U40.7 | length 1.4
  Top Layer w0.508: v1(114.554,-130.048) U40.7@114.554,-128.702
  Bottom Layer w0.254: R338.2@114.554,-130.81 R338.2@114.554,-130.722
NetR350_1: R350.1 R1033.2 U1007.1 | length 15.3
  Top Layer w0.254: U1007.1@111.064,-41.006 109.374,-41.006 108.785,-40.417 R1033.2@108.785,-40.367 108.785,-38.465 109.75,-37.5 115.75,-37.5 116.25,-38 R350.1@119.05,-38
NetR351_1: R351.1 R1040.2 U1007.7 | length 4.3
  Top Layer w0.254: U1007.7@116.564,-42.276 117.432,-42.276 117.808,-41.9 R1040.2@119,-41.9 R351.1@120.75,-41.9
NetR1032_2: R1032.2 R1033.1 U1007.2 | length 3.6
  Top Layer w0.254: R1032.2@107.515,-42.067 107.724,-42.276 U1007.2@111.064,-42.276
NetR1039_2: R1039.2 R1040.1 U1007.6 | length 4
  Top Layer w0.254: U1007.6@116.564,-43.546 118.946,-43.546 R1040.1@119,-43.6 R1039.2@119,-45.15
NetR2002_1: R2002.1 R2006.2 U2002.5 | length 4
  Top Layer w0.254: R2002.1@41.443,-164.06 R2006.2@41.443,-162.86 ; R2002.1@41.581,-164.249 U2002.5@44.367,-164.249
NetR2007_2: R2007.2 R2017.2 U2002.7 | length 5.9
  Top Layer w0.254: R2007.2@41.628,-169.989 41.58,-169.941 R2017.2@41.58,-167.258 42.049,-166.789 U2002.7@44.545,-166.789
NetR2008_1: R2008.1 R2019.2 U2002.1 | length 4.5
  Top Layer w0.254: U2002.1@49.867,-168.059 51.75,-168.059 ; R2008.1@51.698,-170.028 51.698,-168.11 51.75,-168.059 ; R2019.2@52.376,-168.059 51.75,-168.059
NetR2012_2: R2012.2 R2013.1 R2014.2 | length 3.3
  Top Layer w0.254: R2012.2@38.245,-166.864 R2013.1@38.245,-165.484 ; R2012.2@38.245,-166.737 R2012.2@38.171,-166.81 R2014.2@40.018,-166.81
NetR2013_2: R2013.2 R2017.1 U2002.6 | length 4.5
  Top Layer w0.254: R2013.2@40.056,-165.558 40.095,-165.519 U2002.6@44.545,-165.519
NetR2015_2: R2015.2 U2001.4 | length 5
  Top Layer w0.254: R2015.2@22.334,-171.072 23.694,-171.072 24.227,-170.539 24.227,-168.989 24.697,-168.519 U2001.4@25.319,-168.519
NetR2018_2: R2018.2 R2019.1 U2002.2 | length 4.2
  Top Layer w0.254: U2002.2@49.867,-166.789 52.341,-166.789 R2019.1@52.573,-166.556 R2018.2@54.004,-166.556
NetR2021_2: R2021.2 R2023.2 U2004.5 | length 4.4
  Top Layer w0.254: R2023.2@41.392,-177.97 R2021.2@41.392,-179.245 41.506,-179.359 U2004.5@44.367,-179.359 U2004.5@44.52,-179.359
NetR2024_2: R2024.2 R2036.2 U2004.7 | length 5.7
  Top Layer w0.254: R2036.2@41.555,-182.241 R2036.2@41.555,-182.368 ; R2024.2@41.628,-184.794 41.555,-184.721 R2036.2@41.555,-182.368 ; U2004.7@44.52,-181.899 U2004.7@44.367,-181.899 42.024,-181.899 R2036.2@41.555,-182.368
NetR2028_2: R2028.2 R2029.1 R2034.2 | length 3.3
  Top Layer w0.254: R2029.1@38.219,-180.595 38.219,-181.975 38.146,-182.048 R2034.2@39.992,-182.048
NetR2029_2: R2029.2 R2036.1 U2004.6 | length 4.5
  Top Layer w0.254: R2029.2@40.031,-180.668 40.07,-180.629 U2004.6@44.52,-180.629
NetR2030_1: R2030.1 R2038.2 U2004.1 | length 4.5
  Top Layer w0.254: U2004.1@49.867,-183.169 51.795,-183.169 ; R2030.1@51.845,-184.867 51.845,-183.22 51.795,-183.169 ; R2038.2@52.607,-183.265 52.511,-183.169 51.795,-183.169
NetR2035_2: R2035.2 U2003.4 | length 5
  Top Layer w0.254: R2035.2@22.421,-186.187 23.781,-186.187 24.315,-185.653 24.315,-184.104 24.784,-183.634 U2003.4@25.407,-183.634
NetR2037_2: R2037.2 R2038.1 U2004.2 | length 4.4
  Top Layer w0.254: U2004.2@49.867,-181.899 52.273,-181.899 R2038.1@52.607,-181.565 R2037.2@54.004,-181.565 R2037.2@53.95,-181.62
NetR2039_2: R2039.2 R2042.2 U2006.5 | length 4.4
  Top Layer w0.254: R2042.2@41.392,-193.23 41.367,-193.255 41.367,-194.471 41.515,-194.619 U2006.5@44.494,-194.619
NetR2044_2: R2044.2 R2055.2 U2006.7 | length 5.7
  Top Layer w0.254: R2044.2@41.602,-200.13 41.529,-200.057 R2055.2@41.529,-197.628 41.925,-197.628 42.394,-197.159 42.735,-197.159 U2006.7@44.367,-197.159 U2006.7@44.494,-197.159
NetR2046_2: R2046.2 R2047.1 R2052.2 | length 3.3
  Top Layer w0.254: R2047.1@38.194,-195.855 38.194,-197.234 38.121,-197.308 R2052.2@39.967,-197.308
NetR2047_2: R2047.2 R2055.1 U2006.6 | length 4.5
  Top Layer w0.254: R2047.2@40.005,-195.928 40.044,-195.889 U2006.6@44.494,-195.889
NetR2048_1: R2048.1 R2057.2 U2006.1 | length 4.6
  Top Layer w0.254: U2006.1@49.867,-198.429 52.02,-198.429 ; R2048.1@52,-200.227 52,-198.449 52.02,-198.429 ; R2057.2@52.57,-198.22 52.362,-198.429 52.02,-198.429
NetR2054_2: R2054.2 U2005.4 | length 5
  Top Layer w0.254: R2054.2@22.421,-201.427 23.781,-201.427 24.315,-200.893 24.315,-199.344 24.784,-198.874 U2005.4@25.407,-198.874
NetR2056_2: R2056.2 R2057.1 U2006.2 | length 4.4
  Top Layer w0.254: U2006.2@49.867,-197.159 51.295,-197.159 51.845,-196.608 53.916,-196.608 R2056.2@54.004,-196.52
NetTP4_1: TP4.1 U2.69 | length 2.6
  Top Layer w0.254: U2.69@104.096,-191.781 104.096,-193.698 104.5,-194.102 TP4.1@104.5,-194.25
NetTP5_1: TP5.1 U2.68 | length 3.6
  Top Layer w0.254: TP5.1@103.596,-195.404 U2.68@103.596,-191.781
NetTP6_1: TP6.1 U2.67 | length 2.6
  Top Layer w0.254: TP6.1@102.75,-194.25 102.75,-194.172 103.094,-193.828 103.094,-191.784 U2.67@103.096,-191.781
NetTP9_1: TP9.1 U16.139 | length 3
  Top Layer w0.254: TP9.1@90,-99 90.051,-98.949 U16.139@90.051,-95.987
NetTP10_1: TP10.1 U16.140 | length 3.9
  Top Layer w0.254: U16.140@90.551,-95.987 90.551,-98.301 91,-98.75 TP10.1@91,-99.75
NetTP12_1: TP12.1 U2.93 | length 4
  Top Layer w0.254: U2.93@109.096,-181.281 112.634,-181.281 112.852,-181.5 TP12.1@113,-181.5
NetTP13_1: TP13.1 U2.92 | length 2.7
  Top Layer w0.254: U2.92@109.096,-181.781 111.384,-181.781 111.602,-182 TP13.1@111.75,-182
NetTR1_1: TR1.1 U38.6 | length 3.7
  Top Layer w0.508: TR1.1@51.357,-60.29 51.361,-60.286 52.546,-60.286 54.132,-58.7 U38.6@54.357,-58.7
NetTR1_3: TR1.3 U38.4 | length 3.7
  Top Layer w0.508: TR1.3@51.357,-55.21 51.361,-55.214 52.546,-55.214 54.132,-56.8 U38.4@54.357,-56.8
NJTRST: J1.2 R4.1 RJ3.2 U16.134 | length 105.2
  Top Layer w0.254: v1(87.25,-104.5) 87.25,-100 87.551,-99.699 U16.134@87.551,-95.987 ; v1(92.248,-147.252) 92.25,-147.254 92.25,-149.75 95,-152.5 105.25,-152.5 112.5,-159.75 112.5,-165.75 118.034,-171.284 R4.1@118.923,-171.284 121.322,-171.284 J1.2@121.641,-170.965 122.518,-170.088 RJ3.2@127.284,-170.088
  S3 w0.254: v1(87.25,-104.5) 89.5,-104.5 91.75,-106.75 91.75,-146.75 92.248,-147.248 v1(92.248,-147.252)
NJTRST-1: J10.2 J11.2 R147.1 U2.90 | length 38.1
  Top Layer w0.254: U2.90@109.096,-182.781 112.969,-182.781 113.25,-182.5 v1(114.5,-182.5) ; R147.1@119,-192.9 120.821,-192.9 121.601,-192.12 J11.2@121.641,-192.12 121.668,-192.12 127.273,-186.515 J10.2@127.3,-186.515
  S3 w0.254: v1(114.5,-182.5) 114.5,-184 110.5,-188 110.5,-190.75 111.83,-192.08 121.601,-192.08 J11.2@121.641,-192.12
NRST_CPU: C2.2 J1.8 R1.1 RJ3.8 U16.25 | length 136.7
  Top Layer w0.254: v1(92.25,-81.973) 92.991,-81.973 93.226,-81.737 U16.25@94.801,-81.737 ; v1(96,-147.25) 97.5,-148.75 107,-148.75 113.975,-155.725 J1.8@121.641,-155.725 124.5,-158.585 124.5,-161.75 125.218,-162.468 RJ3.8@127.284,-162.468
  S3 w0.254: v1(92.25,-81.973) 92.25,-85.5 89.25,-88.5 78.5,-88.5 77.25,-89.75 77.25,-97 81,-100.75 92.5,-100.75 95.512,-103.762 95.512,-146.762 v1(96,-147.25)
  Bottom Layer w0.254: 92.25,-81.35 v1(92.25,-81.973) 93.677,-81.973 R1.1@93.9,-81.75
NRST_CPU-1: C25.2 J10.8 J11.8 R143.1 U2.14 | length 43.3
  Top Layer w0.254: R143.1@98.5,-173.35 C25.2@100,-173.35 100,-173.4 100.596,-173.996 U2.14@100.596,-175.781 100.596,-178.596 100.75,-178.75 v1(100.75,-179.5) ; J11.8@121.641,-176.88 125.285,-176.88 J10.8@127.3,-178.895
  S3 w0.254: v1(100.75,-179.5) 100.75,-181.75 105.25,-186.25 109.75,-186.25 114.25,-181.75 116.771,-181.75 J11.8@121.641,-176.88
OPD1: R2004.2 R2009.2 SMA2001.1
OPD_REF: R2012.1 U2001.9 | length 9.6
  Top Layer w0.254: U2001.9@28.529,-168.51 R2012.1@38.171,-168.51
OPD_VENV: R2006.1 U2001.10 | length 15.3
  Top Layer w0.254: U2001.10@28.519,-168.019 29.665,-168.019 29.935,-167.75 36,-167.75 37,-166.75 37,-163.5 37.64,-162.86 R2006.1@39.743,-162.86
OPD_VRMS: R2003.1 U2001.11 | length 32
  Top Layer w0.254: U2001.11@28.519,-167.519 29.251,-167.519 29.572,-167.198 35.302,-167.198 36.25,-166.25 36.25,-162.75 37.25,-161.75 53.5,-161.75 54.3,-162.55 54.3,-163.906 R2003.1@54.346,-163.952
org_24V: J4.6 U33.3 | length 10
  Top Layer w0.381: U33.3@129.45,-96.75 129.6,-96.75 129.91,-97.06 130.658,-97.808 J4.6@138.979,-97.808
org_ctrl: R223.2 R298.1 | length 1.5
  Top Layer w0.254: R223.2@109.75,-97.6 R298.1@111.25,-97.6
OUT1_REF: R2005.1 R2014.1 R2016.2 | length 2.8
  Top Layer w0.254: R2005.1@39.945,-171.202 R2005.1@40.018,-171.128 ; R2005.1@40.018,-171.23 R2014.1@40.018,-168.51
OUT2_REF: R2020.1 R2027.2 R2034.1 | length 2.7
  Top Layer w0.254: R2020.1@39.992,-186.468 R2034.1@39.992,-183.748
OUT3: R2040.1
OUT4_REF: R2041.1 R2052.1 R2053.2 | length 2.7
  Top Layer w0.254: R2041.1@39.967,-201.727 R2052.1@39.967,-199.008
OUT_OPD: R2001.1 R2058.2 U10.6 | length 26.3
  Top Layer w0.254: R2058.2@47.199,-171.728 47.272,-171.801 R2001.1@48.54,-171.801 48.54,-173.79 49.5,-174.75 57.25,-174.75 59.75,-172.25 59.75,-166.859 61,-165.609 U10.6@64.094,-165.609
OUT_RPD: R2022.1 R2059.2 U17.6 | length 20.8
  Top Layer w0.254: R2059.2@47.299,-186.567 48.636,-186.567 R2022.1@48.709,-186.64 48.709,-189.209 49.25,-189.75 56.5,-189.75 59.809,-193.059 U17.6@63.954,-193.059
PA_STATE: R228.2 R309.2 U23.13 | length 17.6
  Top Layer w0.254: U23.13@43.336,-122.21 44.71,-122.21 46,-123.5 48.35,-123.5 54.935,-123.5 56.007,-122.428 R309.2@56.007,-119.721 ; 48.35,-123.5 R228.2@48.35,-122.25
Port_D0: R115.2 U2.15 | length 97
  Top Layer w0.254: v1(60.5,-120.75) R115.2@60.5,-119.85 ; v1(100,-179.5) 100,-179.431 100.096,-179.335 U2.15@100.096,-175.781
  S3 w0.254: v1(60.5,-120.75) 60.5,-138.75 85.5,-163.75 85.5,-183.347 87.936,-185.783 95.967,-185.783 100,-181.75 v1(100,-179.5)
Port_D1: R123.2 U2.16 | length 94.8
  Top Layer w0.254: v1(61.75,-120.723) 61.75,-120.427 R123.2@61.75,-119.85 ; v1(99.252,-179.502) 99.252,-178.998 99.596,-178.654 U2.16@99.596,-175.781
  S3 w0.254: v1(61.75,-120.723) 61.75,-138.75 86.163,-163.163 86.163,-183.304 88.143,-185.283 95.217,-185.283 99.252,-181.248 v1(99.252,-179.502)
Port_D2: R142.1 U2.17 | length 92.5
  Top Layer w0.254: v1(63,-120.723) R142.1@63,-119.85 ; v1(98.5,-179.5) 98.5,-179 99.096,-178.404 U2.17@99.096,-175.781
  S3 w0.254: v1(63,-120.723) 63,-138.75 86.793,-162.543 86.793,-183.043 88.5,-184.75 94.75,-184.75 98.5,-181 v1(98.5,-179.5)
Port_D3: R141.1 U2.18 | length 89.8
  Top Layer w0.254: v1(64.25,-120.723) 64.25,-120.427 R141.1@64.25,-119.85 ; v1(97.75,-179.5) 97.75,-179 98.596,-178.154 U2.18@98.596,-175.781
  S3 w0.254: v1(64.25,-120.723) 64.25,-138.75 87.5,-162 87.5,-182.75 88.717,-183.967 94.283,-183.967 97.75,-180.5 v1(97.75,-179.5)
Port_D4: R119.1 U2.33 | length 99.2
  Top Layer w0.254: v1(65.5,-120.723) R119.1@65.5,-119.85 ; U2.33@93.096,-181.281 101.727,-181.281 104,-179.009 v1(104,-179)
  S3 w0.254: v1(65.5,-120.723) 65.5,-138.75 83.5,-156.75 103,-156.75 105,-158.75 105,-172.987 104,-173.987 v1(104,-179)
Port_D5: R113.1 U2.34 | length 99.9
  Top Layer w0.254: v1(66.75,-120.75) R113.1@66.75,-119.85 ; U2.34@93.096,-181.781 102.219,-181.781 v1(104.75,-179.25)
  S3 w0.254: v1(66.75,-120.75) 66.75,-138.75 84,-156 103.25,-156 105.75,-158.5 105.75,-173.487 104.75,-174.487 v1(104.75,-179.25)
Port_D6: R111.1 U2.63 | length 101.5
  Top Layer w0.254: v1(68,-120.723) R111.1@68,-119.85 ; U2.63@101.096,-191.781 101.096,-189.654 103.75,-187 103.75,-181.25 v1(105.5,-179.5)
  S3 w0.254: v1(68,-120.723) 68,-139 84.191,-155.191 103.691,-155.191 106.5,-158 106.5,-173.737 105.5,-174.737 v1(105.5,-179.5)
Port_D7: R100.1 U2.64 | length 101.6
  Top Layer w0.254: v1(69.25,-120.723) R100.1@69.25,-119.85 ; U2.64@101.596,-191.781 101.596,-189.904 104.25,-187.25 104.25,-181.75 v1(106.25,-179.75)
  S3 w0.254: v1(69.25,-120.723) 69.25,-139.25 84.25,-154.25 104,-154.25 107.25,-157.5 107.25,-174.237 106.25,-175.237 v1(106.25,-179.75)
Port_D8: R98.1 U2.65 | length 101.6
  Top Layer w0.254: v1(70.5,-120.723) R98.1@70.5,-119.85 ; U2.65@102.096,-191.781 102.096,-190.154 104.75,-187.5 104.75,-182.25 v1(107,-180)
  S3 w0.254: v1(70.5,-120.723) 70.5,-139.5 84.5,-153.5 104.5,-153.5 108,-157 108,-174.487 107,-175.487 v1(107,-180)
Port_D9: R95.1 U2.66 | length 101.7
  Top Layer w0.254: v1(71.75,-120.723) 71.75,-120.427 R95.1@71.75,-119.85 ; U2.66@102.596,-191.781 102.596,-190.404 105.25,-187.75 105.25,-182.75 v1(107,-181)
  S3 w0.254: v1(71.75,-120.723) 71.75,-139.75 84.75,-152.75 105,-152.75 108.75,-156.5 108.75,-174.737 107.75,-175.737 107.75,-180.25 v1(107,-181)
Port_D10: R94.1 U2.78 | length 100.5
  Top Layer w0.254: v1(73,-120.75) R94.1@73,-119.85 ; v1(107,-182) 105.75,-183.25 105.75,-187.75 106.781,-188.781 U2.78@109.096,-188.781
  S3 w0.254: v1(73,-120.75) 73,-140 85,-152 105.75,-152 109.496,-155.746 109.496,-174.991 108.5,-175.987 108.5,-180.5 v1(107,-182)
Port_D11: R59.1 U2.79 | length 99.5
  Top Layer w0.254: v1(74.25,-120.723) R59.1@74.25,-119.85 ; v1(107,-183) 106.25,-183.75 106.25,-187.25 107.281,-188.281 U2.79@109.096,-188.281
  S3 w0.254: v1(74.25,-120.723) 74.25,-140.25 85.25,-151.25 106.25,-151.25 110.25,-155.25 110.25,-175.237 109.25,-176.237 109.25,-180.75 v1(107,-183)
Port_D12: R47.1 U2.80 | length 98.2
  Top Layer w0.254: v1(75.5,-120.723) R47.1@75.5,-119.85 ; v1(107,-184) 107,-187 107.781,-187.781 U2.80@109.096,-187.781
  S3 w0.254: v1(75.5,-120.723) 75.5,-140.5 85.5,-150.5 106.5,-150.5 111,-155 111,-175.487 110,-176.487 110,-181 v1(107,-184)
Port_D13: R27.1 U2.7 | length 106.9
  Top Layer w0.254: v1(76.75,-120.723) R27.1@76.75,-119.85 ; v1(103.04,-179.04) 104.096,-177.983 U2.7@104.096,-175.781
  S3 w0.254: v1(76.75,-120.723) 76.75,-140.582 85.918,-149.75 107.25,-149.75 111.75,-154.25 111.75,-170.25 113,-171.5 113,-180 108.25,-184.75 106.75,-184.75 103,-181 103,-179.079 v1(103.04,-179.04)
Port_D14: R26.1 U2.8 | length 108.7
  Top Layer w0.254: v1(78,-120.723) R26.1@78,-119.85 ; v1(102.25,-179.5) 102.25,-179.075 103.596,-177.729 U2.8@103.596,-175.781
  S3 w0.254: v1(78,-120.723) 78,-140.75 86.25,-149 107.75,-149 112.5,-153.75 112.5,-169.75 113.5,-170.75 113.5,-180.5 108.75,-185.25 106.5,-185.25 102.25,-181 v1(102.25,-179.5)
Port_D15: R20.1 U2.9 | length 110.7
  Top Layer w0.254: v1(79.25,-120.723) R20.1@79.25,-119.85 ; v1(101.5,-179.5) 101.5,-179.004 103.096,-177.408 U2.9@103.096,-175.781
  S3 w0.254: v1(79.25,-120.723) 79.25,-140.75 86.75,-148.25 108.5,-148.25 113.25,-153 113.25,-169.25 114,-170 114,-181 109.25,-185.75 106,-185.75 101.5,-181.25 v1(101.5,-179.5)
POWER11_LED: D2.1 J5.A5 R19.1 | length 19.1
  Top Layer w0.254: J5.A5@6.666,-28.811 8.727,-26.75 21.9,-26.75 D2.1@22.65,-27.5 R19.1@24.65,-27.5
POWER22_LED: D7.1 J5.B5 R168.1 | length 12.1
  Top Layer w0.254: J5.B5@13.426,-28.811 16.561,-28.811 18,-30.25 21.9,-30.25 D7.1@22.65,-31 R168.1@24.65,-31
power_led_9: D43.1 J5.A2 R25.1 | length 21
  Top Layer w0.254: J5.A2@6.666,-37.121 6.962,-37.416 7.541,-37.416 11.625,-41.5 16.5,-41.5 17.988,-42.988 21.988,-42.988 22.65,-43.65 23.027,-43.273 24.377,-43.273 R25.1@24.65,-43
power_led_10: D44.1 J5.A6 R43.1 | length 26.3
  Top Layer w0.254: J5.A6@3.826,-38.506 3.826,-40.276 6.55,-43 15,-43 18.25,-46.25 21.5,-46.25 D44.1@22.65,-47.4 ; D44.1@22.65,-47.5 D44.1@22.65,-47.4 ; R43.1@24.65,-46 24.6,-46 24.327,-46.273 24.327,-46.323 23.257,-47.393 22.657,-47.393 D44.1@22.65,-47.4
power_led_11: D45.1 J5.A1 R214.1 | length 20.8
  Top Layer w0.254: J5.A1@6.666,-39.891 8.891,-39.891 11.25,-42.25 15.75,-42.25 18,-44.5 21.65,-44.5 D45.1@22.65,-45.5 22.65,-45.4 23.55,-44.5 R214.1@24.65,-44.5
power_led_12: D47.1 J5.B2 R215.1 | length 12.5
  Top Layer w0.254: J5.B2@13.426,-37.121 13.564,-37.258 15.758,-37.258 18,-39.5 22,-39.5 22.65,-40.15 22.8,-40 R215.1@24.65,-40
power_led_13: D20.1 J8.A5 R230.1 | length 21.2
  Top Layer w0.254: J8.A5@6.666,-130.229 10.051,-126.844 16.906,-126.844 19.125,-124.625 22.275,-124.625 D20.1@23.15,-125.5 R230.1@25.15,-125.5
power_led_14: D21.1 J8.A9 R24.2 | length 30
  Top Layer w0.254: J8.A9@3.826,-131.614 4.033,-131.407 4.033,-129.767 8.8,-125 8.8,-121.25 10.05,-120 16.5,-120 17,-120.5 22.25,-120.5 22.952,-121.202 23.15,-121.4 D21.1@23.15,-121.5 R24.2@25.15,-121.5
power_led_15: D22.1 J8.A4 R229.1 | length 22.6
  Top Layer w0.254: J8.A4@6.666,-132.999 8.144,-131.521 8.144,-129.906 10.55,-127.5 18.25,-127.5 19.25,-126.5 22.25,-126.5 23.15,-127.4 D22.1@23.15,-127.5 R229.1@25.15,-127.5
power_led_16: D56.1 J8.A8 R213.1 | length 35.3
  Top Layer w0.254: J8.A8@3.826,-134.384 3.434,-134.384 2.4,-133.35 2.4,-130.4 8.05,-124.75 8.05,-120.75 9.55,-119.25 16.5,-119.25 17.25,-118.5 22.25,-118.5 23.15,-119.4 D56.1@23.15,-119.5 R213.1@25.15,-119.5
power_led_17: D57.1 J8.A2 R231.1 | length 32.8
  Top Layer w0.254: J8.A2@6.666,-138.539 5.3,-137.173 5.3,-129.5 8.55,-126.25 15.75,-126.25 19.5,-122.5 22.25,-122.5 23.15,-123.4 D57.1@23.15,-123.5 R231.1@25.15,-123.5
power_led_18: D58.1 J8.A1 R42.1 | length 47.8
  Top Layer w0.254: J8.A1@6.666,-141.309 6.475,-141.5 2.8,-141.5 1.75,-140.45 1.75,-129.55 7.3,-124 7.3,-120.25 9.3,-118.25 16,-118.25 17.75,-116.5 22.18,-116.5 23.18,-117.5 R42.1@25.15,-117.5 ; D58.1@23.15,-117.75 D58.1@23.15,-117.65
PPS: R200.2 R218.2 R312.2 U12.5 U23.3 | length 79.5
  Top Layer w0.254: R218.2@46.5,-139.8 46.473,-139.773 45.273,-139.773 45,-139.5 U12.5@43.55,-139.5 42.5,-139.5 40.75,-137.75 40.75,-134 38.25,-131.5 36.25,-131.5 34.5,-129.75 34.5,-123.48 ; R200.2@46.65,-116.75 46.6,-116.75 46.327,-117.023 46.327,-117.073 44.655,-118.745 41.505,-118.745 40,-120.25 40,-122.5 39.02,-123.48 U23.3@37.164,-123.48 34.5,-123.48 ; R312.2@53.65,-100.25 43,-100.25 39.75,-103.5 39.75,-117.5 37.75,-119.5 35.75,-119.5 34.5,-120.75 34.5,-123.48
PPS+: D46.2 J8.B7 R183.1 R184.2 | length 20.4
  Top Layer w0.254: J8.B7@10.586,-137.154 10.682,-137.25 15.25,-137.25 16.75,-138.75 20.95,-138.75 D46.2@22.7,-140.5 ; D46.2@22.9,-140.75 R183.1@27.05,-140.75 R184.2@27.05,-143.5
PPS-: J8.B2 R185.2 R187.2 | length 12.1
  Top Layer w0.254: J8.B2@13.426,-138.539 13.445,-138.558 14.808,-138.558 16.231,-139.981 16.231,-143.481 17.5,-144.75 R187.2@19.65,-144.75 R185.2@19.65,-143.5
PTT_SW: R109.2 R176.2 U18.5 | length 6.7
  Top Layer w0.254: R176.2@131.25,-20.9 R109.2@131.25,-19.65
  Top Layer w0.381: U18.5@127.25,-17 127.25,-17.635 129.115,-19.5 R109.2@131.25,-19.5
PWM_Ctrl: D19.2 D68.1 J9.3 R56.1 | length 16.8
  Top Layer w0.254: R56.1@120.7,-36.75 123.75,-36.75 124.25,-37.25 D19.2@125.85,-37.25 ; D19.2@125.85,-37.2 126.823,-36.227 126.873,-36.227 127.6,-35.5 133.75,-35.5 134.899,-34.351 J9.3@136.139,-34.351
